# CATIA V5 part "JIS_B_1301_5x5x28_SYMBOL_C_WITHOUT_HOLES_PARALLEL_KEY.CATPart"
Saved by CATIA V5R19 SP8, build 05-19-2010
Part number: JIS B 1301 KEY 5x5x28 PARALLEL WITHOUT HOLES SYMBOL C
Nomenclature: 69_b
Publications: "Mating Face", "Axis"
Bounding box of the stored display mesh (mm): x 0 to 28, y -3 to 2, z 0 to 5
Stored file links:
  C:\Users\rphgr\Desktop\0_Tapis_TC520B_vitesse\JIS_B_1301_5x5x28_SYMBOL_C_WITHOUT_HOLES_PARALLEL_KEY.CATPart
  C:\MechanicalStandardParts\JIS_Standards\Design_Tables\JIS_B_1301_PARALLEL_KEY_WITHOUT_HOLES_SYMBOL_C.txt
  C:\Program Files\Dassault Systemes\B19\win_b64\startup\components\MechanicalStandardParts\JIS_Standards\Design_Tables\JIS_B_1301_PARALLEL_KEYS_WITHOUT_HOLES_SYMBOL_C.txt
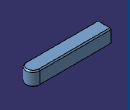
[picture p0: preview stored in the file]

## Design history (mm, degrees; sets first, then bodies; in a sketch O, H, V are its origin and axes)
Parameters
  l_length = 28 mm
  b_width = 5 mm
  h_thickness = 5 mm
  c_chamfer_max = 0.4 mm
Body1 "PartBody" (main body)
  Sketch1 on xy-plane, origin (0, 0, 0), H (1, 0, 0), V (0, 1, 0)
    line L1 (0, -3) -> (25.5, -3)
    line L2 (0, 2) -> (0, -3)
    arc A1 centre (25.5, -0.5) radius 2.5 from (25.5, 2) to (25.5, -3) cw
    point P5 (25.5, -3)
    point P6 (25.5, 2)
    line L3 (25.5, 2) -> (0, 2)
    point P7 (25.5, -3)
    distance L1 H = 3
    distance A1 L2 = 28 {= l_length}
    distance L3 L1 = 5 {= b_width}
    coincidence: V L2, P5 L1, A1 P6, A1 P7
    tangency: A1 L1, L3 A1
  Pad1: profile Sketch1, direction (0, 0, 1), length 5 {= h_thickness}
  Chamfer1: length 0.4 {= c_chamfer_max}, angle 45, on edge [face of Pad1 | face of Pad1] (x6)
